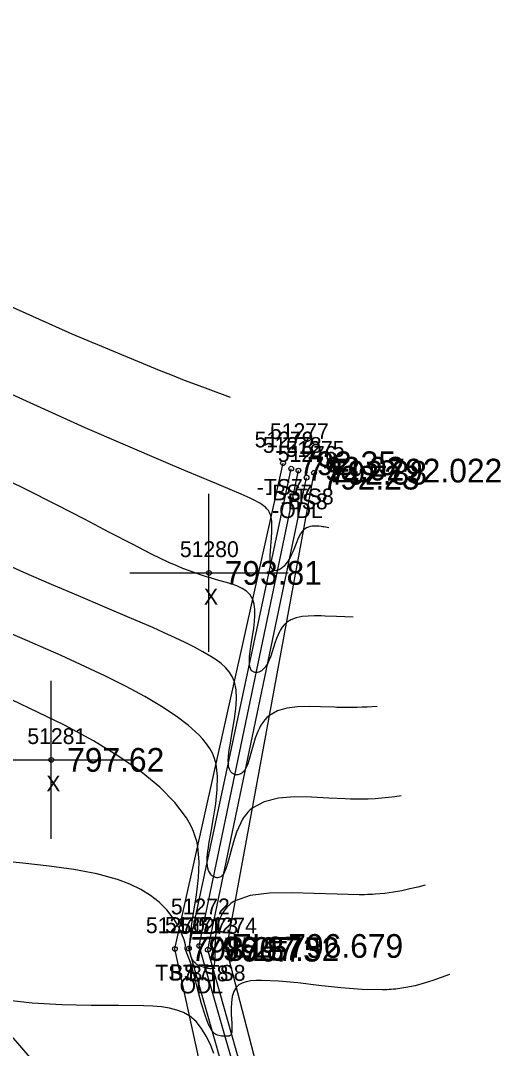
# Model space of a CAD drawing. Extents: x 1378535 to 1380697, y 997729 to 1000024.
# Drawn here: x 1380331.3 to 1380360.9, y 998458.3 to 998523.3 of the extents above; entities that cross this region are included whole.
import ezdxf

# ---------------------------------------------------------------- set-up
doc = ezdxf.new("R2010")
doc.units = 0
for name, color, linetype in [('RD_DTM_BkLn1', 7, 'Continuous'), ('RD_DTM_BkLn2', 7, 'Continuous'), ('RD_DTM_BkLn_txCode', 7, 'Continuous'), ('RD_DTM_Major1', 7, 'Continuous'), ('RD_DTM_Minor1', 7, 'Continuous'), ('RD_EX_H2O', 7, 'Continuous'), ('RD_EX_H2O_txCode', 7, 'Continuous'), ('RD_EX_Misc', 7, 'Continuous'), ('RD_EX_Misc_txCode', 7, 'Continuous'), ('RD_EX_Road', 7, 'Continuous'), ('RD_EX_TX_H2O_ELEV', 7, 'Continuous'), ('RD_EX_TX_Misc_ELEV', 7, 'Continuous'), ('RD_SMD_Locator', 7, 'Continuous')]:
    doc.layers.add(name, color=color, linetype=linetype)

msp = doc.modelspace()

# ---------------------------------------------------------------- linework, layer by layer
at = {"layer": 'RD_DTM_BkLn1'}
msp.add_spline([(1380561.34, 997899.221), (1380543.703, 997960.783), (1380525.014, 998016.596), (1380501.317, 998075.31), (1380476.746, 998129.121), (1380448.822, 998181.196), (1380418.354, 998233.119), (1380383.215, 998285.146), (1380349.465, 998331.418), (1380310.818, 998378.028), (1380271.622, 998420.471), (1380231.531, 998459.847)], degree=3, dxfattribs=at)
at = {"layer": 'RD_DTM_BkLn2'}
for points in [[(1380350.361, 998436.643), (1380337.694, 998451), (1380323.636, 998467.285), (1380260.103, 998510.193)], [(1380342.243, 998378.297), (1380341.222, 998378.794), (1380337.882, 998383.923), (1380339.937, 998394.371), (1380347.246, 998401.635), (1380352.056, 998408.24), (1380354.428, 998415.538), (1380355.168, 998431.333), (1380353.577, 998440.924), (1380344.095, 998450.72), (1380341.062, 998464.56), (1380347.888, 998495.275)], [(1380346.062, 998390.778), (1380352.059, 998398.762), (1380357.223, 998408.109), (1380359.05, 998414.678), (1380357.644, 998430.313), (1380354.857, 998440.685), (1380345.53, 998451.911), (1380341.943, 998464.584), (1380348.407, 998494.93)], [(1380342.252, 998378.302), (1380345.66, 998377.184), (1380355.36, 998385.068), (1380360.528, 998393.384), (1380363.832, 998405.455), (1380365.019, 998412.446), (1380367.523, 998429.074), (1380358.953, 998441.535), (1380347.182, 998453.514), (1380344.309, 998464.547), (1380349.846, 998494.675)], [(1380350.411, 998388.016), (1380357.217, 998396.024), (1380361.046, 998406.719), (1380362.44, 998413.636), (1380360.217, 998430.459), (1380357.666, 998441.235), (1380346.441, 998452.787), (1380343.139, 998464.516), (1380349.375, 998494.362)]]:
    msp.add_lwpolyline(points, dxfattribs=at)
at = {"layer": 'RD_DTM_Major1'}
msp.add_lwpolyline([(1380353.83, 998479.889), (1380353.206, 998479.857), (1380352.889, 998479.843), (1380352.566, 998479.833), (1380352.234, 998479.827), (1380351.892, 998479.826), (1380351.597, 998479.831), (1380351.293, 998479.838), (1380351.138, 998479.843), (1380350.262, 998479.877), (1380349.529, 998479.892), (1380348.811, 998479.868), (1380348.136, 998479.784), (1380347.531, 998479.613), (1380347.026, 998479.333), (1380346.871, 998479.198), (1380346.731, 998479.047), (1380346.606, 998478.881), (1380346.493, 998478.703), (1380346.392, 998478.514), (1380346.301, 998478.316), (1380346.138, 998477.89), (1380346.002, 998477.453), (1380345.771, 998476.624), (1380345.658, 998476.271), (1380345.535, 998475.984), (1380345.488, 998475.902), (1380345.438, 998475.83), (1380345.386, 998475.768), (1380345.334, 998475.715), (1380345.279, 998475.671), (1380345.225, 998475.636), (1380345.162, 998475.606), (1380345.1, 998475.585), (1380345.038, 998475.573), (1380344.976, 998475.57), (1380344.916, 998475.575), (1380344.856, 998475.588), (1380344.82, 998475.599), (1380344.785, 998475.613), (1380344.75, 998475.63), (1380344.717, 998475.651), (1380344.685, 998475.674), (1380344.654, 998475.701), (1380344.598, 998475.762), (1380344.549, 998475.836), (1380344.507, 998475.923), (1380344.474, 998476.026), (1380344.449, 998476.144), (1380344.434, 998476.277), (1380344.43, 998476.485), (1380344.444, 998476.72), (1380344.472, 998476.981), (1380344.513, 998477.264), (1380344.562, 998477.567), (1380344.618, 998477.887), (1380344.726, 998478.492), (1380344.829, 998479.121), (1380344.907, 998479.753), (1380344.944, 998480.367), (1380344.92, 998480.942), (1380344.817, 998481.456), (1380344.679, 998481.793), (1380344.491, 998482.092), (1380344.256, 998482.36), (1380343.98, 998482.605), (1380343.666, 998482.836), (1380343.318, 998483.06), (1380342.828, 998483.347), (1380342.29, 998483.638), (1380341.704, 998483.934), (1380341.071, 998484.238), (1380340.389, 998484.553), (1380339.659, 998484.879), (1380338.21, 998485.508), (1380336.637, 998486.178), (1380334.975, 998486.883), (1380333.257, 998487.617), (1380331.519, 998488.374), (1380329.796, 998489.147)], dxfattribs=at)
at = {"layer": 'RD_DTM_Minor1'}
for points in [[(1380344.58, 998499.421), (1380343.153, 998499.953), (1380342.424, 998500.228), (1380341.675, 998500.514), (1380340.899, 998500.814), (1380340.091, 998501.132), (1380334.562, 998503.437), (1380328.134, 998506.328), (1380321.297, 998509.63), (1380314.544, 998513.166), (1380308.367, 998516.76), (1380303.259, 998520.234), (1380301.396, 998521.739), (1380299.816, 998523.182), (1380298.476, 998524.565)], [(1380350.785, 998491.189), (1380350.465, 998491.246), (1380350.385, 998491.259), (1380350.305, 998491.27), (1380350.149, 998491.289), (1380350.071, 998491.295), (1380349.995, 998491.3), (1380349.918, 998491.301), (1380349.843, 998491.3), (1380349.721, 998491.292), (1380349.602, 998491.273), (1380349.488, 998491.242), (1380349.379, 998491.197), (1380349.277, 998491.136), (1380349.181, 998491.058), (1380349.08, 998490.944), (1380348.989, 998490.807), (1380348.904, 998490.653), (1380348.825, 998490.483), (1380348.75, 998490.303), (1380348.564, 998489.826), (1380348.506, 998489.683), (1380348.445, 998489.542), (1380348.381, 998489.405), (1380348.312, 998489.273), (1380348.26, 998489.183), (1380348.206, 998489.098), (1380348.149, 998489.016), (1380348.051, 998488.889), (1380347.95, 998488.775), (1380347.847, 998488.678), (1380347.744, 998488.597), (1380347.642, 998488.536), (1380347.544, 998488.496), (1380347.485, 998488.482), (1380347.428, 998488.478), (1380347.373, 998488.482), (1380347.322, 998488.497), (1380347.275, 998488.522), (1380347.231, 998488.557), (1380347.204, 998488.587), (1380347.18, 998488.623), (1380347.157, 998488.663), (1380347.137, 998488.709), (1380347.12, 998488.76), (1380347.105, 998488.817), (1380347.073, 998489.076), (1380347.072, 998489.396), (1380347.091, 998489.762), (1380347.154, 998490.561), (1380347.178, 998490.961), (1380347.183, 998491.13), (1380347.185, 998491.293), (1380347.181, 998491.45), (1380347.172, 998491.599), (1380347.155, 998491.74), (1380347.131, 998491.87), (1380347.089, 998492.02), (1380347.032, 998492.155), (1380346.961, 998492.276), (1380346.875, 998492.386), (1380346.775, 998492.489), (1380346.659, 998492.585), (1380346.548, 998492.664), (1380346.425, 998492.742), (1380346.291, 998492.82), (1380346.143, 998492.898), (1380345.983, 998492.978), (1380345.809, 998493.061), (1380345.237, 998493.319), (1380344.543, 998493.618), (1380343.717, 998493.965), (1380342.747, 998494.368), (1380341.625, 998494.836), (1380340.339, 998495.378), (1380335.398, 998497.516), (1380329.34, 998500.263)], [(1380352.308, 998485.539), (1380351.263, 998485.58), (1380350.548, 998485.61), (1380350.293, 998485.618), (1380349.885, 998485.625), (1380349.48, 998485.613), (1380349.089, 998485.575), (1380348.722, 998485.499), (1380348.391, 998485.376), (1380348.104, 998485.195), (1380347.965, 998485.065), (1380347.842, 998484.915), (1380347.733, 998484.75), (1380347.636, 998484.571), (1380347.55, 998484.381), (1380347.471, 998484.183), (1380347.374, 998483.905), (1380347.284, 998483.624), (1380347.198, 998483.348), (1380347.112, 998483.085), (1380347.022, 998482.843), (1380346.923, 998482.628), (1380346.886, 998482.56), (1380346.847, 998482.497), (1380346.806, 998482.438), (1380346.765, 998482.383), (1380346.722, 998482.332), (1380346.679, 998482.286), (1380346.6, 998482.212), (1380346.519, 998482.152), (1380346.438, 998482.105), (1380346.357, 998482.071), (1380346.278, 998482.05), (1380346.2, 998482.042), (1380346.153, 998482.043), (1380346.107, 998482.05), (1380346.063, 998482.062), (1380346.021, 998482.08), (1380345.981, 998482.103), (1380345.943, 998482.133), (1380345.902, 998482.177), (1380345.864, 998482.231), (1380345.832, 998482.294), (1380345.805, 998482.368), (1380345.784, 998482.452), (1380345.769, 998482.547), (1380345.76, 998482.783), (1380345.776, 998483.06), (1380345.811, 998483.373), (1380345.859, 998483.713), (1380345.975, 998484.446), (1380346.034, 998484.855), (1380346.081, 998485.26), (1380346.107, 998485.653), (1380346.104, 998486.025), (1380346.062, 998486.364), (1380345.974, 998486.663), (1380345.808, 998486.948), (1380345.579, 998487.177), (1380345.297, 998487.362), (1380344.971, 998487.513), (1380344.611, 998487.642), (1380344.227, 998487.757), (1380343.683, 998487.912), (1380343.496, 998487.966), (1380343.305, 998488.021), (1380343.111, 998488.08), (1380342.748, 998488.195), (1380342.372, 998488.324), (1380341.98, 998488.468), (1380341.57, 998488.628), (1380341.139, 998488.808), (1380340.685, 998489.008), (1380339.58, 998489.535), (1380338.334, 998490.169), (1380336.93, 998490.902), (1380335.354, 998491.729), (1380333.59, 998492.642), (1380331.624, 998493.635), (1380327.519, 998495.634)], [(1380355.353, 998474.239), (1380354.954, 998474.188), (1380354.551, 998474.14), (1380354.138, 998474.097), (1380353.713, 998474.062), (1380353.269, 998474.037), (1380352.802, 998474.026), (1380352.484, 998474.027), (1380352.154, 998474.035), (1380351.812, 998474.048), (1380350.774, 998474.106), (1380349.69, 998474.162), (1380348.614, 998474.171), (1380347.596, 998474.088), (1380346.691, 998473.869), (1380345.949, 998473.47), (1380345.801, 998473.342), (1380345.664, 998473.203), (1380345.538, 998473.052), (1380345.422, 998472.891), (1380345.316, 998472.722), (1380345.217, 998472.544), (1380344.957, 998471.955), (1380344.753, 998471.337), (1380344.586, 998470.729), (1380344.441, 998470.167), (1380344.3, 998469.692), (1380344.147, 998469.34), (1380344.087, 998469.251), (1380344.024, 998469.182), (1380343.958, 998469.13), (1380343.891, 998469.095), (1380343.823, 998469.074), (1380343.755, 998469.067), (1380343.713, 998469.068), (1380343.672, 998469.074), (1380343.631, 998469.084), (1380343.591, 998469.097), (1380343.551, 998469.114), (1380343.512, 998469.133), (1380343.465, 998469.162), (1380343.419, 998469.195), (1380343.376, 998469.233), (1380343.304, 998469.313), (1380343.24, 998469.411), (1380343.186, 998469.528), (1380343.144, 998469.665), (1380343.114, 998469.824), (1380343.098, 998470.007), (1380343.097, 998470.17), (1380343.105, 998470.347), (1380343.121, 998470.539), (1380343.144, 998470.743), (1380343.173, 998470.961), (1380343.209, 998471.191), (1380343.346, 998471.981), (1380343.498, 998472.844), (1380343.637, 998473.741), (1380343.73, 998474.634), (1380343.748, 998475.482), (1380343.66, 998476.249), (1380343.563, 998476.606), (1380343.43, 998476.935), (1380343.262, 998477.243), (1380343.061, 998477.536), (1380342.828, 998477.818), (1380342.564, 998478.097), (1380341.914, 998478.683), (1380341.133, 998479.28), (1380340.217, 998479.89), (1380339.165, 998480.518), (1380337.974, 998481.165), (1380336.643, 998481.837), (1380333.874, 998483.124), (1380330.784, 998484.463)], [(1380356.875, 998468.589), (1380356.393, 998468.469), (1380355.903, 998468.353), (1380355.398, 998468.246), (1380354.869, 998468.152), (1380354.31, 998468.076), (1380353.712, 998468.022), (1380353.549, 998468.012), (1380353.383, 998468.004), (1380353.214, 998467.997), (1380353.042, 998467.993), (1380352.866, 998467.99), (1380352.688, 998467.988), (1380351.313, 998468.016), (1380349.855, 998468.077), (1380348.397, 998468.117), (1380347.024, 998468.087), (1380345.82, 998467.934), (1380344.871, 998467.607), (1380344.776, 998467.552), (1380344.685, 998467.494), (1380344.599, 998467.432), (1380344.518, 998467.367), (1380344.441, 998467.299), (1380344.369, 998467.229), (1380344.084, 998466.864), (1380343.877, 998466.455), (1380343.737, 998466.018), (1380343.65, 998465.569), (1380343.603, 998465.122), (1380343.583, 998464.694), (1380343.579, 998464.466), (1380343.574, 998464.054), (1380343.568, 998463.874), (1380343.558, 998463.715), (1380343.54, 998463.58), (1380343.531, 998463.536), (1380343.52, 998463.496), (1380343.508, 998463.46), (1380343.494, 998463.427), (1380343.478, 998463.399), (1380343.46, 998463.375), (1380343.436, 998463.351), (1380343.41, 998463.334), (1380343.38, 998463.321), (1380343.331, 998463.311), (1380343.275, 998463.309), (1380343.214, 998463.316), (1380343.147, 998463.328), (1380343.074, 998463.345), (1380342.995, 998463.365), (1380342.865, 998463.402), (1380342.728, 998463.447), (1380342.589, 998463.504), (1380342.454, 998463.579), (1380342.329, 998463.674), (1380342.218, 998463.794), (1380342.182, 998463.847), (1380342.148, 998463.903), (1380342.119, 998463.964), (1380342.066, 998464.111), (1380342.03, 998464.279), (1380342.008, 998464.467), (1380341.999, 998464.675), (1380342.003, 998464.9), (1380342.017, 998465.143), (1380342.116, 998465.996), (1380342.264, 998466.961), (1380342.42, 998467.994), (1380342.54, 998469.049), (1380342.582, 998470.08), (1380342.503, 998471.043), (1380342.436, 998471.368), (1380342.348, 998471.68), (1380342.239, 998471.982), (1380342.109, 998472.277), (1380341.958, 998472.566), (1380341.788, 998472.852), (1380341.059, 998473.82), (1380340.103, 998474.788), (1380338.924, 998475.757), (1380337.524, 998476.731), (1380335.907, 998477.714), (1380334.076, 998478.707), (1380330.767, 998480.305)], [(1380358.398, 998462.94), (1380357.877, 998462.747), (1380357.349, 998462.561), (1380356.805, 998462.389), (1380356.238, 998462.238), (1380355.64, 998462.116), (1380355.003, 998462.029), (1380354.865, 998462.016), (1380354.726, 998462.004), (1380354.585, 998461.995), (1380354.441, 998461.987), (1380354.296, 998461.981), (1380354.148, 998461.977), (1380352.879, 998462.004), (1380351.53, 998462.11), (1380350.16, 998462.258), (1380348.829, 998462.41), (1380347.596, 998462.529), (1380346.519, 998462.576), (1380346.168, 998462.567), (1380345.849, 998462.538), (1380345.565, 998462.485), (1380345.316, 998462.403), (1380345.107, 998462.288), (1380344.937, 998462.134), (1380344.775, 998461.868), (1380344.675, 998461.545), (1380344.625, 998461.183), (1380344.611, 998460.801), (1380344.621, 998460.418), (1380344.652, 998459.872), (1380344.66, 998459.705), (1380344.664, 998459.552), (1380344.662, 998459.417), (1380344.652, 998459.302), (1380344.633, 998459.21), (1380344.616, 998459.166), (1380344.596, 998459.131), (1380344.573, 998459.103), (1380344.546, 998459.082), (1380344.516, 998459.066), (1380344.484, 998459.055), (1380344.446, 998459.048), (1380344.407, 998459.044), (1380344.364, 998459.044), (1380344.228, 998459.049), (1380344.076, 998459.052), (1380343.998, 998459.055), (1380343.918, 998459.063), (1380343.838, 998459.079), (1380343.757, 998459.104), (1380343.7, 998459.128), (1380343.643, 998459.159), (1380343.587, 998459.198), (1380343.53, 998459.246), (1380343.474, 998459.303), (1380343.419, 998459.371), (1380343.186, 998459.785), (1380342.961, 998460.37), (1380342.742, 998461.085), (1380342.525, 998461.89), (1380342.309, 998462.743), (1380342.091, 998463.604), (1380341.903, 998464.09), (1380341.705, 998464.561), (1380341.721, 998464.812), (1380341.634, 998465.146), (1380341.497, 998465.499), (1380341.346, 998465.836), (1380341.286, 998465.954), (1380341.225, 998466.069), (1380341.162, 998466.183), (1380341.096, 998466.294), (1380341.027, 998466.403), (1380340.956, 998466.51), (1380340.546, 998467.039), (1380340.068, 998467.518), (1380339.519, 998467.947), (1380338.9, 998468.328), (1380338.208, 998468.662), (1380337.443, 998468.951), (1380336.13, 998469.31), (1380334.673, 998469.587), (1380333.107, 998469.806), (1380331.464, 998469.989), (1380329.777, 998470.159)], [(1380343.527, 998457.955), (1380343.302, 998458.517), (1380343.044, 998459.051), (1380342.745, 998459.541), (1380342.397, 998459.968), (1380341.992, 998460.318), (1380341.612, 998460.536), (1380341.189, 998460.699), (1380340.723, 998460.815), (1380340.214, 998460.892), (1380339.662, 998460.94), (1380339.068, 998460.968), (1380337.504, 998460.99), (1380335.769, 998460.993), (1380333.927, 998461.024), (1380332.044, 998461.129), (1380330.186, 998461.354)]]:
    msp.add_lwpolyline(points, dxfattribs=at)
at = {"layer": 'RD_EX_H2O'}
msp.add_lwpolyline([(1380344.835, 998382.427), (1380346.443, 998386.456), (1380349.047, 998388.512), (1380354.505, 998397.042), (1380358.892, 998407.075), (1380360.627, 998414.107), (1380358.934, 998429.835), (1380356.187, 998440.788), (1380346.104, 998452.475), (1380342.6, 998464.751), (1380348.858, 998494.808)], dxfattribs=at)
at = {"layer": 'RD_EX_Misc'}
for p, q in [((1380343.208, 998483.34), (1380343.208, 998493.34)), ((1380338.208, 998488.34), (1380348.208, 998488.34)), ((1380333.252, 998471.519), (1380333.252, 998481.519)), ((1380328.252, 998476.519), (1380338.252, 998476.519))]:
    msp.add_line(p, q, dxfattribs=at)
at = {"layer": 'RD_EX_Road'}
for points in [[(1380571.276, 997900.848), (1380553.838, 997963.229), (1380535.074, 998018.791), (1380510.809, 998079.184), (1380486.363, 998133.158), (1380458.393, 998185.941), (1380428.109, 998238.221), (1380392.689, 998291.143), (1380357.52, 998337.623), (1380319.367, 998385.164), (1380279.255, 998428.684), (1380239.596, 998468.129), (1380183.367, 998518.832)], [(1380551.892, 997897.33), (1380534.244, 997958.196), (1380514.831, 998013.467), (1380491.083, 998070.746), (1380467.518, 998124.397), (1380439.882, 998176.529), (1380409.174, 998228.123), (1380375.886, 998278.447), (1380340.748, 998326.222), (1380303.332, 998371.138), (1380263.981, 998413.97), (1380224.662, 998452.644), (1380168.713, 998504.787)]]:
    msp.add_spline(points, degree=3, dxfattribs=at)
at = {"layer": 'RD_SMD_Locator'}
for centre in [(1380347.888, 998495.275), (1380348.407, 998494.93), (1380348.858, 998494.808), (1380349.846, 998494.675), (1380349.375, 998494.362), (1380343.208, 998488.34), (1380333.252, 998476.519), (1380342.6, 998464.751), (1380341.062, 998464.56), (1380341.943, 998464.584), (1380343.139, 998464.516), (1380344.309, 998464.547)]:
    msp.add_circle(centre, 0.15, dxfattribs=at)

# ---------------------------------------------------------------- texts
at = {"layer": 'RD_DTM_BkLn_txCode'}
for s, p in [('51279', (1380346.093, 998496.275)), ('51278', (1380346.612, 998495.93)), ('51276', (1380347.556, 998495.362)), ('51275', (1380348.051, 998495.675)), ('-TS7', (1380346.234, 998493.275)), ('-BS7', (1380346.769, 998492.93)), ('-TS8', (1380348.192, 998492.675)), ('-BS8', (1380347.737, 998492.362)), ('51270', (1380339.227, 998465.56)), ('51271', (1380340.431, 998465.584)), ('51273', (1380341.344, 998465.516)), ('51274', (1380342.514, 998465.547)), ('TS7', (1380339.818, 998462.56)), ('BS7', (1380340.715, 998462.584)), ('BS8', (1380341.911, 998462.516)), ('TS8', (1380343.065, 998462.547))]:
    msp.add_text(s, height=1, dxfattribs=at).set_placement(p)
at = {"layer": 'RD_EX_H2O_txCode'}
for s, p in [('51277', (1380347.063, 998496.808)), ('-ODL', (1380347.204, 998491.808)), ('51272', (1380340.805, 998466.751)), ('ODL', (1380341.356, 998461.751))]:
    msp.add_text(s, height=1, dxfattribs=at).set_placement(p)
at = {"layer": 'RD_EX_Misc_txCode'}
for s, p in [('51280', (1380341.373, 998489.34)), ('X', (1380342.893, 998486.34)), ('51281', (1380331.74, 998477.519)), ('X', (1380332.937, 998474.519))]:
    msp.add_text(s, height=1, dxfattribs=at).set_placement(p)
at = {"layer": 'RD_EX_TX_H2O_ELEV'}
for s, p in [('EL=792.022', (1380350.858, 998494.058)), ('EL=796.679', (1380344.6, 998464.001))]:
    msp.add_text(s, height=1.5, dxfattribs=at).set_placement(p)
at = {"layer": 'RD_EX_TX_Misc_ELEV'}
for s, p in [('792.35', (1380348.888, 998494.525)), ('792.02', (1380349.407, 998494.18)), ('792.38', (1380350.846, 998493.925)), ('792.23', (1380350.375, 998493.612)), ('793.81', (1380344.208, 998487.59)), ('797.62', (1380334.252, 998475.769)), ('798.25', (1380342.062, 998463.81)), ('796.87', (1380342.943, 998463.834)), ('796.73', (1380344.139, 998463.766)), ('797.52', (1380345.309, 998463.797))]:
    msp.add_text(s, height=1.5, dxfattribs=at).set_placement(p)

doc.saveas('drawing.dxf')
